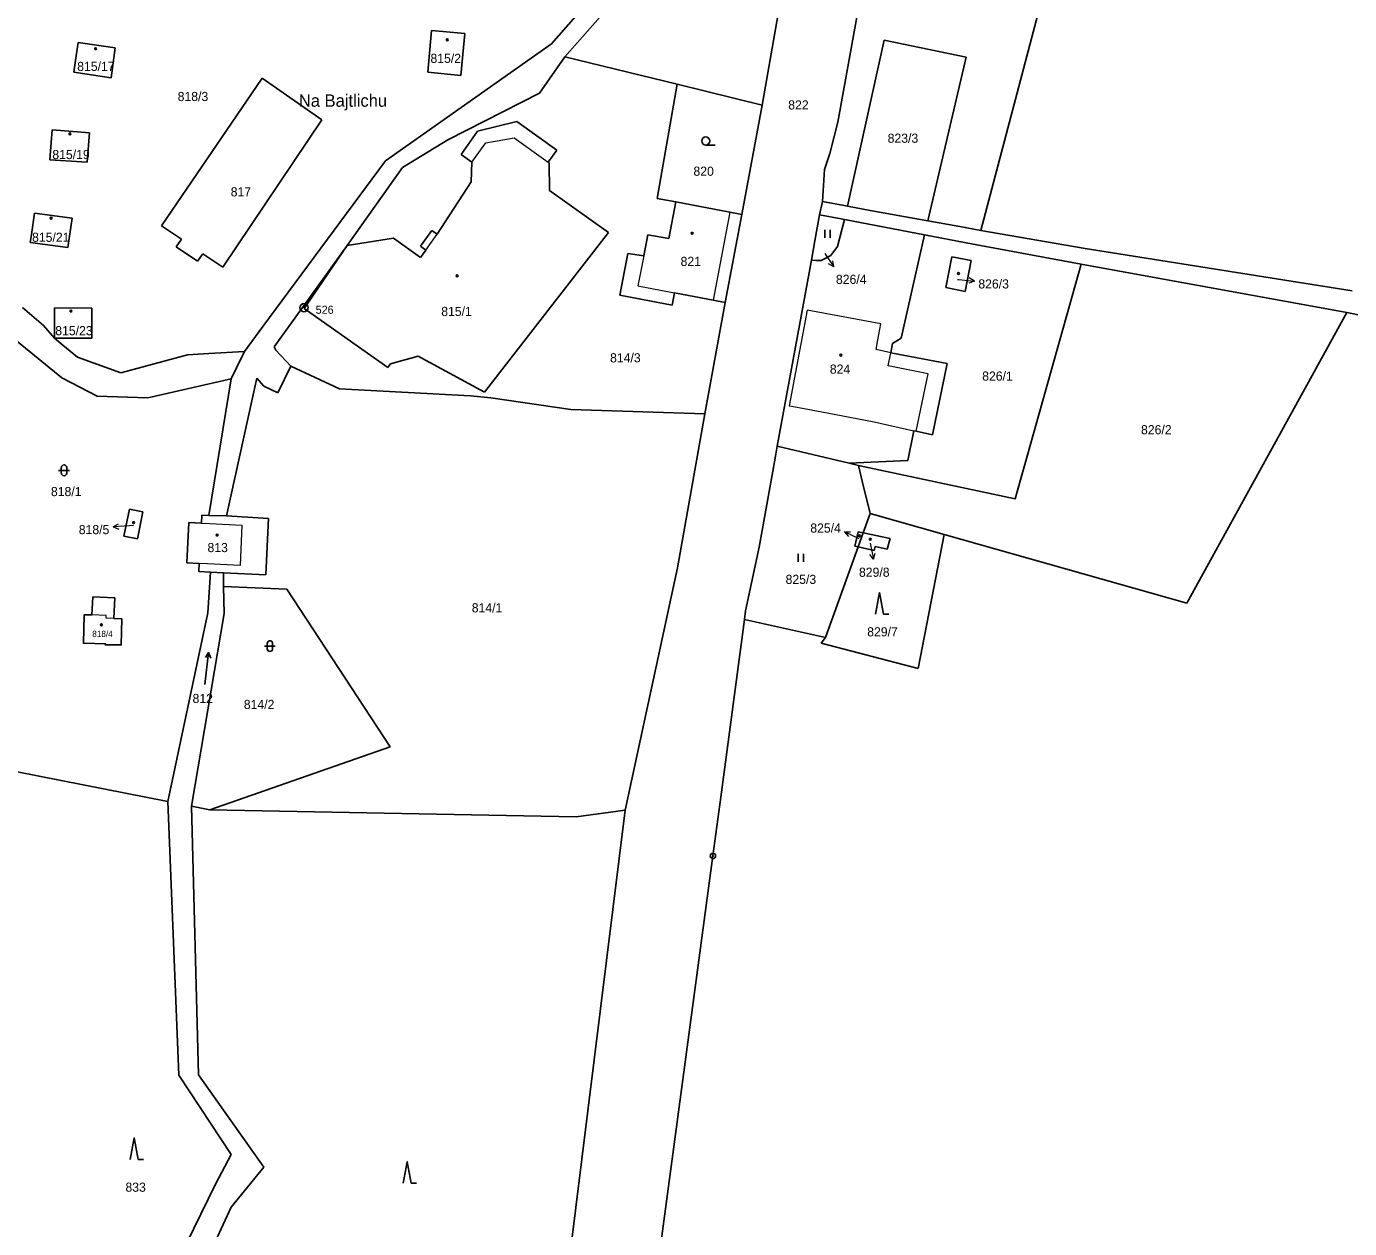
# Model space of a CAD drawing. Extents: x -727701 to -724405, y -960481 to -957284.
# Drawn here: x -727505.9 to -727259.8, y -959556.8 to -959333.1 of the extents above; entities that cross this region are included whole.
import ezdxf
from ezdxf.enums import TextEntityAlignment as Align

# ---------------------------------------------------------------- set-up
doc = ezdxf.new("R2010")
doc.units = 0
doc.header["$LTSCALE"] = 0.68
for name, color, linetype, lineweight in [('1', 7, 'Continuous', 25), ('3', 7, 'Continuous', 25), ('4', 7, 'Continuous', 13), ('5', 7, 'Continuous', 25), ('7', 7, 'Continuous', 13), ('8', 7, 'Continuous', 25)]:
    doc.layers.add(name, color=color, linetype=linetype, lineweight=lineweight)
doc.layers.add('2', color=7, linetype='Continuous')

msp = doc.modelspace()

# ---------------------------------------------------------------- linework, layer by layer
at = {"layer": '1'}
for p, q in [((-727292.14, -959233.61), (-727328.4, -959371.05)), ((-727359.19, -959291.2), (-727369.06, -959347.75)), ((-727344.75, -959294.36), (-727355.02, -959350.92)), ((-727408.27, -959336.35), (-727395.09, -959321.33)), ((-727405.74, -959338.75), (-727392.56, -959323.74)), ((-727430.54, -959333.85), (-727431.23, -959341.62)), ((-727427.78, -959334.1), (-727430.54, -959333.85)), ((-727424.37, -959334.4), (-727427.78, -959334.1)), ((-727425.08, -959342.27), (-727424.37, -959334.4)), ((-727496.61, -959338.56), (-727496.27, -959336.09)), ((-727496.27, -959336.09), (-727489.35, -959337.1)), ((-727489.35, -959337.1), (-727490.1, -959342.66)), ((-727439.1, -959358.11), (-727408.27, -959336.35)), ((-727346.37, -959335.69), (-727353.2, -959366.57)), ((-727331.16, -959338.84), (-727346.37, -959335.69)), ((-727497.04, -959341.62), (-727496.61, -959338.56)), ((-727410.46, -959345.55), (-727405.74, -959338.75)), ((-727384.9, -959343.86), (-727405.74, -959338.75)), ((-727338.28, -959369.29), (-727331.16, -959338.84)), ((-727490.1, -959342.66), (-727497.04, -959341.62)), ((-727431.23, -959341.62), (-727425.08, -959342.27)), ((-727480.78, -959370.18), (-727462.06, -959342.71)), ((-727462.06, -959342.71), (-727450.97, -959350.49)), ((-727384.9, -959343.86), (-727388.59, -959365.11)), ((-727369.06, -959347.75), (-727384.9, -959343.86)), ((-727427.51, -959354.23), (-727410.46, -959345.55)), ((-727369.06, -959347.75), (-727372.87, -959368.12)), ((-727450.97, -959350.49), (-727469.38, -959377.91)), ((-727414.7, -959350.83), (-727421.99, -959352.61)), ((-727407.26, -959356.13), (-727414.7, -959350.83)), ((-727355.02, -959350.92), (-727356.46, -959356.73)), ((-727501.12, -959352.37), (-727501.3, -959354.72)), ((-727494.16, -959352.9), (-727501.12, -959352.37)), ((-727494.59, -959358.39), (-727494.16, -959352.9)), ((-727435.96, -959359.36), (-727427.51, -959354.23)), ((-727421.99, -959352.61), (-727425.07, -959356.94)), ((-727501.3, -959354.72), (-727501.55, -959357.91)), ((-727425.07, -959356.94), (-727423.03, -959358.39)), ((-727408.85, -959358.36), (-727407.26, -959356.13)), ((-727356.46, -959356.73), (-727357.45, -959359.73)), ((-727501.55, -959357.91), (-727494.59, -959358.39)), ((-727461.91, -959388.94), (-727439.1, -959358.11)), ((-727446.21, -959373.84), (-727435.96, -959359.36)), ((-727423.03, -959358.39), (-727423.16, -959362.01)), ((-727408.69, -959358.48), (-727408.85, -959358.36)), ((-727408.63, -959363.62), (-727408.69, -959358.48)), ((-727357.45, -959359.73), (-727357.85, -959365.67)), ((-727423.16, -959362.01), (-727429.49, -959371.77)), ((-727397.62, -959371.45), (-727408.63, -959363.62)), ((-727385.13, -959365.77), (-727388.59, -959365.11)), ((-727386.42, -959372.56), (-727385.13, -959365.77)), ((-727385.13, -959365.77), (-727375.07, -959367.68)), ((-727357.85, -959365.67), (-727358.38, -959368.16)), ((-727357.85, -959365.67), (-727353.81, -959366.45)), ((-727353.81, -959366.45), (-727353.2, -959366.57)), ((-727353.2, -959366.57), (-727348.99, -959367.38)), ((-727504.96, -959371.81), (-727504.37, -959367.85)), ((-727504.37, -959367.85), (-727497.4, -959368.76)), ((-727497.4, -959368.76), (-727498.16, -959374.21)), ((-727372.87, -959368.12), (-727375.92, -959384.46)), ((-727372.87, -959368.12), (-727375.07, -959367.68)), ((-727358.38, -959368.16), (-727359.26, -959372.97)), ((-727358.38, -959368.16), (-727354.38, -959368.92)), ((-727353.76, -959369.04), (-727355.07, -959374.04)), ((-727348.99, -959367.38), (-727338.28, -959369.29)), ((-727332.31, -959370.36), (-727338.28, -959369.29)), ((-727505.18, -959373.3), (-727504.96, -959371.81)), ((-727477.06, -959372.7), (-727480.78, -959370.18)), ((-727430.51, -959371.05), (-727432.61, -959374)), ((-727429.49, -959371.77), (-727430.51, -959371.05)), ((-727420.69, -959401.14), (-727397.62, -959371.45)), ((-727328.4, -959371.05), (-727332.31, -959370.36)), ((-727309.01, -959374.43), (-727328.4, -959371.05)), ((-727498.16, -959374.21), (-727505.18, -959373.3)), ((-727478.01, -959374.1), (-727477.06, -959372.7)), ((-727474.05, -959376.79), (-727478.01, -959374.1)), ((-727459.82, -959392.74), (-727446.21, -959373.84)), ((-727446.21, -959373.84), (-727454.26, -959385.58)), ((-727437.64, -959372.53), (-727446.21, -959373.84)), ((-727432.59, -959376.12), (-727437.64, -959372.53)), ((-727432.61, -959374), (-727431.59, -959374.72)), ((-727391.08, -959375.81), (-727390.32, -959371.9)), ((-727390.32, -959371.9), (-727386.42, -959372.56)), ((-727359.26, -959372.97), (-727359.92, -959376.57)), ((-727355.07, -959374.04), (-727356.27, -959375.7)), ((-727343.2, -959391.08), (-727338.88, -959371.88)), ((-727331.12, -959373.36), (-727338.88, -959371.88)), ((-727329.12, -959373.74), (-727331.12, -959373.36)), ((-727309.75, -959377.32), (-727329.12, -959373.74)), ((-727473.1, -959375.39), (-727474.05, -959376.79)), ((-727469.38, -959377.91), (-727473.1, -959375.39)), ((-727431.59, -959374.72), (-727432.59, -959376.12)), ((-727395.56, -959383.08), (-727394.04, -959375.33)), ((-727394.04, -959375.33), (-727391.08, -959375.81)), ((-727359.92, -959376.57), (-727366.27, -959411.23)), ((-727359.09, -959376.66), (-727359.92, -959376.57)), ((-727358.1, -959376.63), (-727359.09, -959376.66)), ((-727356.27, -959375.7), (-727358.1, -959376.63)), ((-727334.9, -959381.71), (-727333.79, -959375.96)), ((-727333.79, -959375.96), (-727330.22, -959376.65)), ((-727330.22, -959376.65), (-727331.33, -959382.41)), ((-727259.34, -959382.33), (-727309.01, -959374.43)), ((-727309.75, -959377.32), (-727322, -959421.02)), ((-727260.35, -959386.31), (-727309.75, -959377.32)), ((-727385.78, -959384.95), (-727395.56, -959383.08)), ((-727385.35, -959382.65), (-727385.78, -959384.95)), ((-727378.18, -959384.01), (-727385.35, -959382.65)), ((-727375.92, -959384.46), (-727378.18, -959384.01)), ((-727331.33, -959382.41), (-727334.9, -959381.71)), ((-727506.63, -959385.4), (-727502.7, -959388.76)), ((-727500.69, -959385.45), (-727500.69, -959391.1)), ((-727493.7, -959385.51), (-727500.69, -959385.45)), ((-727493.7, -959391.08), (-727493.7, -959385.51)), ((-727454.26, -959385.58), (-727438.65, -959396.56)), ((-727375.92, -959384.46), (-727379.73, -959405.21)), ((-727260.35, -959386.31), (-727290.13, -959440.44)), ((-727168.21, -959405.85), (-727260.35, -959386.31)), ((-727511.22, -959388.79), (-727499.31, -959398.47)), ((-727502.7, -959388.76), (-727500.69, -959391.1)), ((-727465.34, -959393.58), (-727461.91, -959388.94)), ((-727500.69, -959391.1), (-727493.7, -959391.08)), ((-727500.69, -959391.1), (-727499.12, -959392.4)), ((-727344.86, -959392.1), (-727343.2, -959391.08)), ((-727499.12, -959392.4), (-727496.38, -959394.63)), ((-727475.91, -959394.22), (-727471.95, -959393.98)), ((-727471.95, -959393.98), (-727465.34, -959393.58)), ((-727466.81, -959396.62), (-727465.34, -959393.58)), ((-727459.51, -959393.32), (-727459.82, -959392.74)), ((-727456.74, -959396.32), (-727459.51, -959393.32)), ((-727345.17, -959393.81), (-727344.86, -959392.1)), ((-727334.66, -959395.83), (-727345.17, -959393.81)), ((-727496.38, -959394.63), (-727488.31, -959397.57)), ((-727488.31, -959397.57), (-727475.91, -959394.22)), ((-727456.74, -959396.32), (-727459.15, -959401.25)), ((-727447.68, -959400.54), (-727456.74, -959396.32)), ((-727438.65, -959396.56), (-727438.2, -959395.91)), ((-727438.2, -959395.91), (-727433.05, -959394.43)), ((-727433.05, -959394.43), (-727420.69, -959401.14)), ((-727337.38, -959409.1), (-727334.66, -959395.83)), ((-727499.31, -959398.47), (-727492.7, -959401.91)), ((-727483.32, -959402.23), (-727467.81, -959398.7)), ((-727471.95, -959424.13), (-727467.81, -959398.7)), ((-727463.04, -959398.55), (-727468.69, -959424.16)), ((-727467.81, -959398.7), (-727466.81, -959396.62)), ((-727461.71, -959400.07), (-727463.04, -959398.55)), ((-727459.15, -959401.25), (-727461.71, -959400.07)), ((-727423.3, -959401.83), (-727447.68, -959400.54)), ((-727492.7, -959401.91), (-727483.32, -959402.23)), ((-727423.3, -959401.83), (-727419.52, -959402.23)), ((-727404.67, -959404.36), (-727419.52, -959402.23)), ((-727379.73, -959405.21), (-727404.67, -959404.36)), ((-727379.73, -959405.21), (-727384.84, -959433.84)), ((-727341.96, -959413.86), (-727340.87, -959408.34)), ((-727340.87, -959408.34), (-727340.41, -959408.43)), ((-727340.41, -959408.43), (-727337.38, -959409.1)), ((-727366.6, -959413.05), (-727366.79, -959414.14)), ((-727366.27, -959411.23), (-727366.6, -959413.05)), ((-727352.9, -959414.39), (-727366.27, -959411.23)), ((-727366.79, -959414.14), (-727369.61, -959430)), ((-727352.9, -959414.39), (-727341.96, -959413.86)), ((-727351.18, -959414.79), (-727352.9, -959414.39)), ((-727333.09, -959418.65), (-727351.18, -959414.79)), ((-727351.18, -959414.79), (-727350.4, -959417.99)), ((-727350.4, -959417.99), (-727348.99, -959423.73)), ((-727322, -959421.02), (-727333.09, -959418.65)), ((-727487.76, -959427.96), (-727486.72, -959422.9)), ((-727486.72, -959422.9), (-727484.25, -959423.41)), ((-727484.25, -959423.41), (-727485.23, -959428.46)), ((-727476.05, -959432.93), (-727475.67, -959425.4)), ((-727475.67, -959425.4), (-727473.35, -959425.51)), ((-727473.35, -959425.51), (-727473.27, -959424.02)), ((-727473.27, -959424.02), (-727471.95, -959424.13)), ((-727471.95, -959424.13), (-727468.69, -959424.16)), ((-727468.69, -959424.16), (-727460.84, -959424.66)), ((-727460.84, -959424.66), (-727461.39, -959435.17)), ((-727348.99, -959423.73), (-727350.28, -959427.32)), ((-727348.99, -959423.73), (-727335.22, -959427.64)), ((-727485.23, -959428.46), (-727487.76, -959427.96)), ((-727351.22, -959427.11), (-727351.84, -959429.82)), ((-727350.28, -959427.32), (-727351.24, -959429.96)), ((-727350.28, -959427.32), (-727351.22, -959427.11)), ((-727345.28, -959428.38), (-727350.28, -959427.32)), ((-727345.81, -959430.37), (-727345.28, -959428.38)), ((-727335.22, -959427.64), (-727340.08, -959452.57)), ((-727335.22, -959427.64), (-727290.13, -959440.44)), ((-727369.61, -959430), (-727372.15, -959441.81)), ((-727351.24, -959429.96), (-727357.3, -959446.78)), ((-727351.84, -959429.82), (-727351.24, -959429.96)), ((-727351.24, -959429.96), (-727348.23, -959430.63)), ((-727348.23, -959430.63), (-727348.07, -959429.87)), ((-727348.07, -959429.87), (-727345.81, -959430.37)), ((-727473.74, -959433.04), (-727476.05, -959432.93)), ((-727473.82, -959434.54), (-727473.74, -959433.04)), ((-727473.82, -959434.54), (-727471.64, -959434.65)), ((-727472.15, -959442.18), (-727471.64, -959434.65)), ((-727471.64, -959434.65), (-727469.26, -959434.77)), ((-727469.21, -959437.34), (-727469.26, -959434.77)), ((-727469.26, -959434.77), (-727461.39, -959435.17)), ((-727384.84, -959433.84), (-727394.56, -959478.91)), ((-727469.1, -959442.34), (-727469.21, -959437.34)), ((-727457.46, -959437.83), (-727469.21, -959437.34)), ((-727438.24, -959467.17), (-727457.46, -959437.83)), ((-727493.55, -959439.25), (-727493.7, -959442.61)), ((-727479.6, -959477.32), (-727472.15, -959442.18)), ((-727475.18, -959478.19), (-727469.1, -959442.34)), ((-727372.37, -959443.48), (-727372.15, -959441.81)), ((-727376.74, -959476.5), (-727372.37, -959443.48)), ((-727372.37, -959443.48), (-727357.3, -959446.78)), ((-727358.11, -959447.84), (-727357.3, -959446.78)), ((-727340.08, -959452.57), (-727358.11, -959447.84)), ((-727471.75, -959478.87), (-727438.24, -959467.17)), ((-727479.6, -959477.32), (-727511.47, -959471.05)), ((-727479.6, -959477.32), (-727477.56, -959528.2)), ((-727378.22, -959487.43), (-727376.74, -959476.5)), ((-727475.18, -959478.19), (-727473.86, -959528.17)), ((-727471.75, -959478.87), (-727475.18, -959478.19)), ((-727403.67, -959480.14), (-727471.75, -959478.87)), ((-727394.56, -959478.91), (-727417.29, -959662.23)), ((-727394.56, -959478.91), (-727403.67, -959480.14)), ((-727378.22, -959487.43), (-727398.93, -959641.16)), ((-727477.56, -959528.2), (-727467.79, -959543.01)), ((-727473.86, -959528.17), (-727461.76, -959545.37)), ((-727467.79, -959543.01), (-727470.75, -959548.48)), ((-727461.76, -959545.37), (-727467.81, -959552.81)), ((-727470.75, -959548.48), (-727488.42, -959584.85)), ((-727467.81, -959552.81), (-727484.14, -959588.21))]:
    msp.add_line(p, q, dxfattribs=at)
for points in [[(-727354.38, -959368.92), (-727353.76, -959369.04), (-727338.88, -959371.88)], [(-727493.55, -959439.25), (-727489.46, -959439.43), (-727489.63, -959443.28)], [(-727493.7, -959442.61), (-727495.13, -959442.56), (-727495.29, -959447.88), (-727491.16, -959448), (-727491.22, -959448.17), (-727488.25, -959448.18), (-727488.15, -959443.34), (-727489.63, -959443.28)]]:
    msp.add_lwpolyline(points, dxfattribs=at)
at = {"layer": '3'}
for p, q in [((-727379.563, -959355.18), (-727377.813, -959355.18)), ((-727357.411, -959372.47), (-727357.411, -959370.97)), ((-727356.41, -959372.47), (-727356.41, -959370.97)), ((-727499.891, -959415.701), (-727497.889, -959415.701)), ((-727499.391, -959415.201), (-727499.391, -959416.202)), ((-727498.389, -959416.202), (-727498.389, -959415.201)), ((-727362.381, -959432.74), (-727362.381, -959431.24)), ((-727361.38, -959432.74), (-727361.38, -959431.24)), ((-727346.49, -959442.44), (-727345.494, -959442.44)), ((-727461.101, -959447.901), (-727461.101, -959448.902)), ((-727460.099, -959448.902), (-727460.099, -959447.901)), ((-727471.994, -959449.606), (-727471.615, -959450.637)), ((-727461.601, -959448.401), (-727459.599, -959448.401)), ((-727485.09, -959543.9), (-727484.094, -959543.9)), ((-727434.32, -959548.34), (-727433.324, -959548.34))]:
    msp.add_line(p, q, dxfattribs=at)
for points in [[(-727346.49, -959442.44), (-727347.24, -959438.44), (-727347.99, -959442.44)], [(-727472.725, -959455.562), (-727471.994, -959449.606), (-727472.611, -959450.515)], [(-727485.09, -959543.9), (-727485.84, -959539.9), (-727486.59, -959543.9)], [(-727434.32, -959548.34), (-727435.07, -959544.34), (-727435.82, -959548.34)]]:
    msp.add_lwpolyline(points, dxfattribs=at)
msp.add_circle((-727379.5629, -959354.4298), 0.75, dxfattribs=at)
for centre, start, end in [((-727498.89, -959415.2009), 0, 180), ((-727498.89, -959416.2009), 180, 359.98789), ((-727460.6, -959447.9009), 0, 180), ((-727460.6, -959448.9009), 180, 359.98789)]:
    msp.add_arc(centre, 0.5, start, end, dxfattribs=at)
at = {"layer": '4'}
for p, q in [((-727420.47, -959354.79), (-727415.2, -959353.85)), ((-727415.2, -959353.85), (-727408.85, -959358.36)), ((-727423.03, -959358.39), (-727420.47, -959354.79)), ((-727375.07, -959367.68), (-727378.18, -959384.01)), ((-727431.59, -959374.72), (-727429.49, -959371.77)), ((-727391.08, -959375.81), (-727392.17, -959381.35)), ((-727392.17, -959381.35), (-727385.35, -959382.65)), ((-727360.69, -959385.87), (-727364.07, -959403.67)), ((-727347, -959388.47), (-727360.69, -959385.87)), ((-727347.56, -959391.45), (-727347, -959388.47)), ((-727347.9, -959393.22), (-727347.56, -959391.45)), ((-727345.17, -959393.81), (-727347.9, -959393.22)), ((-727345.62, -959396.23), (-727345.17, -959393.81)), ((-727338.18, -959397.76), (-727345.62, -959396.23)), ((-727340.41, -959408.43), (-727338.18, -959397.76)), ((-727364.07, -959403.67), (-727363.23, -959403.83)), ((-727363.23, -959403.83), (-727356.99, -959405.03)), ((-727356.99, -959405.03), (-727348.23, -959406.69)), ((-727348.23, -959406.69), (-727340.87, -959408.34)), ((-727473.35, -959425.51), (-727471.79, -959425.59)), ((-727471.79, -959425.59), (-727465.83, -959425.9)), ((-727465.83, -959425.9), (-727466.14, -959433.43)), ((-727472.18, -959433.12), (-727473.74, -959433.04)), ((-727466.14, -959433.43), (-727472.18, -959433.12))]:
    msp.add_line(p, q, dxfattribs=at)
msp.add_lwpolyline([(-727489.63, -959443.28), (-727491.08, -959443.22), (-727491.06, -959442.69), (-727493.7, -959442.61)], dxfattribs=at)
at = {"layer": '5'}
for centre in [(-727493.0168, -959337.2492), (-727427.6168, -959335.5992), (-727497.7868, -959353.1092), (-727501.2868, -959368.7792), (-727382.0868, -959371.5992), (-727332.5668, -959379.0792), (-727425.7968, -959379.5292), (-727497.5968, -959386.0592), (-727354.4268, -959394.2592), (-727485.9468, -959425.4292), (-727470.4268, -959427.7392), (-727350.9868, -959427.8792), (-727348.9568, -959428.5292), (-727491.9468, -959444.4492)]:
    msp.add_circle(centre, 0.175, dxfattribs=at)
at = {"layer": '7'}
for p, q in [((-727355.752, -959377.818), (-727355.897, -959376.708)), ((-727329.605, -959380.494), (-727330.549, -959379.891)), ((-727489.724, -959426.219), (-727488.69, -959426.649)), ((-727353.74, -959427.162), (-727353.044, -959428.039)), ((-727348.366, -959432.205), (-727348.084, -959431.122))]:
    msp.add_line(p, q, dxfattribs=at)
for points in [[(-727357.43, -959375.33), (-727355.752, -959377.818), (-727356.727, -959377.268)], [(-727332.73, -959380.17), (-727332.59, -959380.18), (-727329.605, -959380.494), (-727330.654, -959380.887)], [(-727485.99, -959425.96), (-727486.73, -959426.01), (-727489.724, -959426.219), (-727488.76, -959425.65)], [(-727351.02, -959428.43), (-727353.74, -959427.162), (-727352.621, -959427.131)], [(-727348.99, -959429.27), (-727348.366, -959432.205), (-727349.064, -959431.33)]]:
    msp.add_lwpolyline(points, dxfattribs=at)
at = {"layer": '8'}
for centre, radius in [((-727454.27, -959385.4298), 0.75), ((-727454.27, -959385.4298), 0.03), ((-727378.22, -959487.4299), 0.5), ((-727378.22, -959487.4299), 0.0303)]:
    msp.add_circle(centre, radius, dxfattribs=at)

# ---------------------------------------------------------------- texts
at = {"layer": '2'}
for s, p in [('815/17', (-727496.44, -959341.395)), ('815/2', (-727430.75, -959339.895)), ('818/3', (-727477.76, -959346.995)), ('822', (-727364.22, -959348.565)), ('815/19', (-727501.06, -959357.795)), ('820', (-727381.85, -959360.895)), ('817', (-727467.9, -959364.735)), ('815/21', (-727504.83, -959373.185)), ('821', (-727384.24, -959377.675)), ('826/4', (-727355.35, -959381.015)), ('826/3', (-727328.87, -959381.862)), ('815/1', (-727428.75, -959386.985)), ('815/23', (-727500.52, -959390.565)), ('814/3', (-727397.35, -959395.615)), ('826/2', (-727298.62, -959408.995)), ('813', (-727472.21, -959430.915)), ('814/1', (-727423.07, -959442.125)), ('812', (-727474.99, -959458.995)), ('814/2', (-727465.46, -959460.105)), ('833', (-727487.47, -959549.915))]:
    msp.add_text(s, height=1.7, dxfattribs=at).set_placement(p)
for s, height, p in [('823/3', 1.7, (-727342.89, -959354.755)), ('824', 1.7, (-727354.589, -959397.715)), ('826/1', 1.7, (-727325.31, -959399.015)), ('818/1', 1.7, (-727498.48, -959420.495)), ('825/3', 1.7, (-727361.87, -959436.835)), ('829/8', 1.7, (-727348.22, -959435.505)), ('818/4', 1.139, (-727491.74, -959446.694)), ('829/7', 1.7, (-727346.69, -959446.595))]:
    msp.add_text(s, height=height, dxfattribs=at).set_placement(p, align=Align.CENTER)
for s, p in [('818/5', (-727490.46, -959427.572)), ('825/4', (-727354.43, -959427.285))]:
    msp.add_text(s, height=1.7, dxfattribs=at).set_placement(p, align=Align.RIGHT)
at = {"layer": '7'}
msp.add_text('Na Bajtlichu', height=2.3, dxfattribs=at).set_placement((-727447.02, -959348.055), align=Align.CENTER)
at = {"layer": '8'}
msp.add_text('526', height=1.5, dxfattribs=at).set_placement((-727452.1, -959386.575))

doc.saveas('drawing.dxf')
